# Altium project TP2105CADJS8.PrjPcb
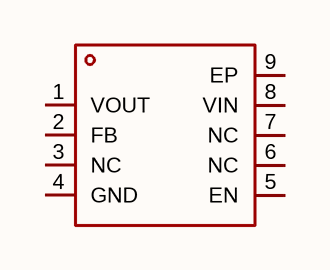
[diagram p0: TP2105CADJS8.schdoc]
1 sheet, 1 parts. Net scope: global (net labels, ports and power ports of the same name join across sheets).

## Sheet TP2105CADJS8.schdoc
size 127 x 101 mm

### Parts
U?  tp2105cadjs8  [ESOP-8_L4.9-W3.9-P1.27-LS6.0-BL-EP3.1]  (value not drawn)

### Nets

Not connected (* = marked no-connect by the designer): U? 1(VOUT) 2(FB) 3(NC) 4(GND) 5(EN) 6(NC) 7(NC) 8(VIN) 9(EP)

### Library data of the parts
U? = tp2105cadjs8: 输出极性:正极;工作电压:100V;输出电流:50mA;电源纹波抑制比(PSRR):-;输出类型:可调;; Manufacturer: TECH PUBLIC(台舟); AddInBom: yes; ModelId: d54f4b6565a44e96be97b48ca144b2c3; ModelTransform: 192.913,236.22,0,0,0,0,0,0,0; Output Configuration: 正极; Voltage - Supply: 100V; Output Current: 50mA; Voltage Dropout: 2.8V; standby current: 23uA; Output Type: 可调; Number of Outputs: 1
